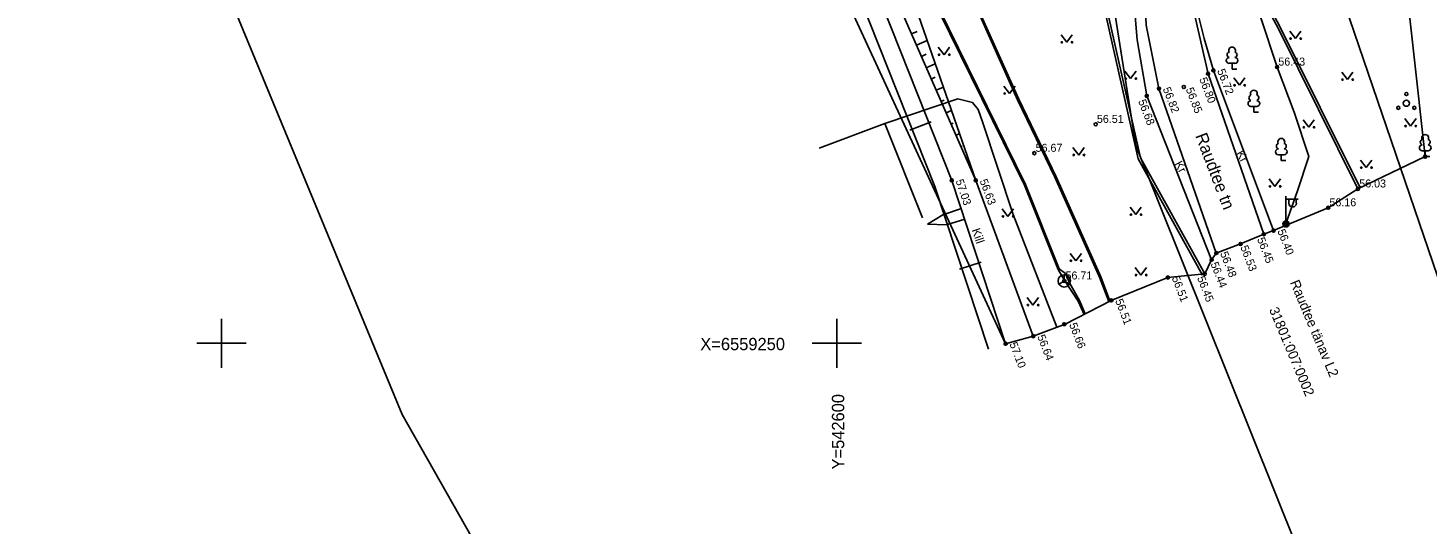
# Model space of a CAD drawing. Extents: x 542320 to 543602, y 6558748 to 6559969.
# Drawn here: x 542534.3 to 542647.9, y 6559235.3 to 6559275.6 of the extents above; entities that cross this region are included whole.
import ezdxf

# ---------------------------------------------------------------- set-up
doc = ezdxf.new("R2010")
doc.units = 0
for name, color, linetype in [('HALJASTUS', 7, 'Continuous'), ('KORGUS-EH2000', 7, 'Continuous'), ('KPKAABEL', 7, 'Continuous'), ('mootpiir', 7, 'Continuous'), ('MPKAABEL', 7, 'Continuous'), ('PIIR', 7, 'Continuous'), ('POST', 7, 'Continuous'), ('PUU', 7, 'Continuous'), ('RDT', 7, 'Continuous'), ('RELJEEF', 7, 'Continuous'), ('SIKAEV', 7, 'Continuous'), ('SITRASS', 7, 'Continuous'), ('TEE', 7, 'Continuous'), ('VORK', 7, 'Continuous')]:
    doc.layers.add(name, color=color, linetype=linetype)

# ---------------------------------------------------------------- blocks, each defined once
blk = doc.blocks.new('VKORIS')
for p, q in [((0, 4), (0, -4)), ((-4, 0), (4, 0))]:
    blk.add_line(p, q)
blk = doc.blocks.new('SIKAEV')
for p, q in [((0, 0), (-0.83, -0.55)), ((0, 1), (0, 0)), ((0, 0), (0.83, -0.55))]:
    blk.add_line(p, q)
blk.add_circle((0, 0), 1)
blk = doc.blocks.new('LEHTP1')
for p, q in [((0.48, 0.95), (-0.48, 0.95)), ((0, 0), (0, 0.95)), ((0.76, 0), (0, 0))]:
    blk.add_line(p, q)
for centre, radius, start, end in [((-0.34, 2.35), 0.465, 109.0217, 253.1415), ((0, 3.04), 0.554, 332.5799, 207.4201), ((0.34, 2.35), 0.465, 286.8508, 70.9859), ((-0.47, 1.42), 0.475, 90.0016, 269.3953), ((0.47, 1.42), 0.475, 270.6047, 89.9984)]:
    blk.add_arc(centre, radius, start, end)
blk = doc.blocks.new('PQQSAS')
for centre, radius in [((0, 0), 0.5), ((0, 1.5), 0.25), ((-1.3, -0.75), 0.25), ((1.3, -0.75), 0.25)]:
    blk.add_circle(centre, radius)
blk = doc.blocks.new('MEPOST')
for radius in [0.5, 0.45, 0.4, 0.35, 0.3, 0.25, 0.2, 0.15, 0.1, 0.05]:
    blk.add_circle((0, 0), radius)
blk = doc.blocks.new('VAPOST')
for p, q in [((0, 0.5), (0, 4.5)), ((0, 4), (2, 4)), ((0.45, 3.36), (0.45, 4)), ((1.68, 3.36), (1.68, 4))]:
    blk.add_line(p, q)
blk.add_arc((1.07, 3.36), 0.613, 180, 0)
blk = doc.blocks.new('MURU')
for p, q in [((-0.93, 1.21), (0, 0)), ((0, 0), (0.89, 1.21))]:
    blk.add_line(p, q)
for centre in [(-0.8, 0), (0.86, 0)]:
    blk.add_circle(centre, 0.11)
blk = doc.blocks.new('RING02')
blk.add_circle((0, 0), 0.25)

msp = doc.modelspace()

# ---------------------------------------------------------------- linework, layer by layer
at = {"layer": 'KPKAABEL'}
for points in [[(542592.52, 6559362.45), (542597.55, 6559351.95), (542600.14, 6559344.37), (542606.12, 6559332.4), (542610.86, 6559323.16), (542616.27, 6559312.94), (542622.06, 6559301.81), (542626.97, 6559292.38), (542631.61, 6559283.75), (542633.96, 6559279.16), (542635.84, 6559275.61), (542642.33, 6559262.55)], [(542592.7, 6559362.53), (542597.73, 6559352.02), (542600.32, 6559344.44), (542606.3, 6559332.49), (542611.03, 6559323.25), (542616.45, 6559313.04), (542622.24, 6559301.9), (542627.15, 6559292.48), (542631.79, 6559283.85), (542634.14, 6559279.25), (542636.01, 6559275.7), (542642.5, 6559262.64)], [(542629.71, 6559255.55), (542624.46, 6559265.01), (542621.33, 6559279), (542619.56, 6559289.35), (542615.6, 6559299.12), (542610.38, 6559310.03), (542605.39, 6559319.87), (542600.37, 6559330.02), (542596.98, 6559338.2), (542596.38, 6559342.12), (542596.81, 6559346.97), (542595.76, 6559350.64), (542591.14, 6559359.29), (542590.25, 6559360.8)], [(542629.88, 6559255.64), (542624.65, 6559265.09), (542621.53, 6559279.04), (542619.76, 6559289.41), (542615.79, 6559299.2), (542610.56, 6559310.12), (542605.57, 6559319.96), (542600.55, 6559330.11), (542597.18, 6559338.25), (542596.58, 6559342.13), (542597.01, 6559346.99), (542595.94, 6559350.72), (542591.32, 6559359.39), (542590.42, 6559360.9)]]:
    msp.add_lwpolyline(points, dxfattribs=at)
at = {"layer": 'mootpiir'}
msp.add_lwpolyline([(542580.6, 6559350.5), (542576.13, 6559347.21), (542573.57, 6559344.25), (542570.53, 6559343.48), (542613.7, 6559249.97), (542615.95, 6559250.58), (542618.55, 6559251.55), (542622.29, 6559253.49), (542626.88, 6559255.35), (542629.88, 6559255.64), (542630.44, 6559256.8), (542630.82, 6559257.34), (542632.79, 6559258.08), (542634.68, 6559258.87), (542635.47, 6559259.16), (542639.91, 6559261.02), (542642.33, 6559262.55), (542647.79, 6559265.18), (542644.8, 6559292.13), (542641.56, 6559300.61), (542636.85, 6559320.34), (542627.62, 6559356.73)], dxfattribs=at)
at = {"layer": 'MPKAABEL'}
for p, q in [((542609.81, 6559269.89), (542603.89, 6559267.86)), ((542609.81, 6559269.89), (542603.89, 6559267.86)), ((542611.02, 6559269.59), (542609.81, 6559269.89)), ((542611.02, 6559269.59), (542609.81, 6559269.89)), ((542611.46, 6559269.02), (542611.02, 6559269.59)), ((542611.46, 6559269.02), (542611.02, 6559269.59)), ((542611.82, 6559268.01), (542611.46, 6559269.02)), ((542611.82, 6559268.01), (542611.46, 6559269.02)), ((542603.89, 6559267.86), (542598.56, 6559265.87)), ((542603.89, 6559267.86), (542598.56, 6559265.87)), ((542606.96, 6559260.19), (542603.89, 6559267.86)), ((542606.96, 6559260.19), (542603.89, 6559267.86)), ((542614.31, 6559260.47), (542611.82, 6559268.01)), ((542614.31, 6559260.47), (542611.82, 6559268.01)), ((542608.59, 6559260.44), (542610.12, 6559260.97)), ((542617.86, 6559251.3), (542614.31, 6559260.47)), ((542617.86, 6559251.3), (542614.31, 6559260.47)), ((542607.36, 6559259.69), (542608.59, 6559260.44)), ((542607.36, 6559259.69), (542608.59, 6559260.44)), ((542607.36, 6559259.69), (542608.89, 6559259.62)), ((542607.36, 6559259.69), (542608.89, 6559259.62)), ((542608.89, 6559259.62), (542610.4, 6559260.08))]:
    msp.add_line(p, q, dxfattribs=at)
for points in [[(542622.09, 6559253.39), (542621.33, 6559255.37), (542617.71, 6559263.5), (542614.68, 6559269.79), (542611.09, 6559277.81), (542606.04, 6559289.6), (542605.82, 6559290.91), (542605.06, 6559292.01), (542601.33, 6559298.32), (542596.16, 6559308.1), (542592.3, 6559315.73), (542590.05, 6559320.2), (542585.68, 6559328.5), (542583.04, 6559333.5), (542580.39, 6559338.55), (542578.35, 6559342.4), (542575.83, 6559346.87)], [(542622.18, 6559253.44), (542621.43, 6559255.41), (542617.8, 6559263.54), (542614.77, 6559269.84), (542611.18, 6559277.85), (542606.14, 6559289.62), (542605.91, 6559290.95), (542605.15, 6559292.07), (542601.41, 6559298.37), (542596.24, 6559308.15), (542592.39, 6559315.78), (542590.14, 6559320.24), (542585.77, 6559328.55), (542583.13, 6559333.54), (542580.48, 6559338.6), (542578.44, 6559342.45), (542575.9, 6559346.95)], [(542636.48, 6559259.71), (542637.41, 6559262.41), (542638.34, 6559265.2), (542637.15, 6559268.8), (542635.76, 6559272.46), (542634.44, 6559276.46)]]:
    msp.add_lwpolyline(points, dxfattribs=at)
at = {"layer": 'PIIR'}
for points in [[(542661.19, 6559057.3), (542631.86, 6559131.08), (542623.73, 6559151.51), (542622.55, 6559153.44), (542596.44, 6559196.28), (542582.74, 6559212.35), (542564.67, 6559244.2), (542533.12, 6559320.57), (542531.79, 6559323.45), (542465.95, 6559465.71), (542406.39, 6559583.67)], [(542456.68, 6559581.07), (542523.83, 6559477.46), (542537.52, 6559453.62), (542591.81, 6559358.92), (542597.79, 6559348.5), (542599.76, 6559343.89), (542619.08, 6559298.96), (542624.28, 6559266.08), (542637.46, 6559233.17), (542680, 6559143.81), (542700.43, 6559093.84), (542700.92, 6559090.29), (542704.02, 6559067.82)], [(542632.63, 6559302.87), (542612.16, 6559350.51), (542632.02, 6559361.13), (542651.63, 6559324.28), (542646.33, 6559321.44), (542665.85, 6559284.72), (542671.39, 6559287.65), (542689.34, 6559253.48), (542704.9, 6559215.47), (542674.63, 6559203.23), (542672.45, 6559208.6), (542665.71, 6559205.86), (542632.63, 6559302.87)], [(542612.16, 6559350.51), (542632.63, 6559302.87), (542665.71, 6559205.86), (542667.87, 6559200.49), (542682.31, 6559164.31), (542683.94, 6559160.9), (542699.54, 6559124.27), (542718.47, 6559078.4), (542700.92, 6559090.29), (542700.43, 6559093.84), (542680, 6559143.81), (542637.46, 6559233.17), (542624.28, 6559266.08), (542619.08, 6559298.96), (542599.76, 6559343.89), (542612.16, 6559350.51)]]:
    msp.add_lwpolyline(points, dxfattribs=at)
at = {"layer": 'RDT'}
for points in [[(542570.53, 6559343.48), (542587.32, 6559311.76), (542594.42, 6559298.32), (542600.93, 6559284.44), (542609.33, 6559263.25), (542613.7, 6559249.97)], [(542569.24, 6559342.8), (542586.03, 6559311.08), (542593.11, 6559297.67), (542599.58, 6559283.86), (542607.95, 6559262.76), (542612.31, 6559249.52)], [(542605.93, 6559267.32), (542607.66, 6559268)], [(542609.96, 6559256.02), (542611.73, 6559256.6)]]:
    msp.add_lwpolyline(points, dxfattribs=at)
at = {"layer": 'RELJEEF'}
for points in [[(542611.28, 6559263.25), (542601.77, 6559284.94), (542595.44, 6559298.86), (542588.13, 6559312.87), (542578.07, 6559334.39), (542577.88, 6559336.16), (542579.74, 6559338.2), (542583.57, 6559340.23), (542588.18, 6559342.44), (542591.62, 6559344.19)], [(542591.62, 6559344.19), (542589.04, 6559341.17), (542585.55, 6559339.38), (542581.61, 6559337.24), (542580.48, 6559335.13), (542584.56, 6559325.43), (542590.14, 6559315.73), (542599.48, 6559301.09), (542603.51, 6559285.65), (542611.28, 6559263.25)], [(542606.06, 6559275.15), (542606.53, 6559275.36)], [(542606.46, 6559274.24), (542607.33, 6559274.62)], [(542606.86, 6559273.32), (542607.26, 6559273.5)], [(542607.26, 6559272.4), (542607.99, 6559272.72)], [(542607.66, 6559271.49), (542607.99, 6559271.63)], [(542608.06, 6559270.57), (542608.65, 6559270.83)], [(542608.47, 6559269.66), (542608.72, 6559269.77)], [(542608.87, 6559268.74), (542609.3, 6559268.93)], [(542609.27, 6559267.82), (542609.45, 6559267.9)], [(542609.67, 6559266.91), (542609.96, 6559267.04)], [(542610.07, 6559265.99), (542610.18, 6559266.04)], [(542610.47, 6559265.08), (542610.62, 6559265.14)]]:
    msp.add_lwpolyline(points, dxfattribs=at)
at = {"layer": 'SITRASS'}
for points in [[(542620.08, 6559252.35), (542619.61, 6559253.42), (542618.45, 6559255.17), (542617.97, 6559256.01), (542615.23, 6559262.86), (542599.65, 6559294.6), (542592.25, 6559308.15), (542591.92, 6559308.73), (542590.02, 6559312.16), (542581.41, 6559328.23), (542578.73, 6559334.14), (542575.62, 6559340.11), (542573.23, 6559344.17)], [(542620.17, 6559252.39), (542619.7, 6559253.47), (542618.92, 6559254.85), (542618.56, 6559255.68), (542618.06, 6559256.05), (542615.33, 6559262.9), (542599.74, 6559294.65), (542592.34, 6559308.19), (542592.29, 6559308.9), (542591.74, 6559309.32), (542590.11, 6559312.21), (542581.5, 6559328.28), (542578.82, 6559334.18), (542575.71, 6559340.16), (542573.33, 6559344.19)]]:
    msp.add_lwpolyline(points, dxfattribs=at)
at = {"layer": 'TEE'}
for points in [[(542624.1, 6559367.1), (542623.09, 6559366.62), (542619.66, 6559364.74), (542606.49, 6559357.53), (542598.93, 6559352.72), (542596.39, 6559351.26), (542597.48, 6559348.27), (542599.1, 6559344.51), (542601.52, 6559338.8), (542604.02, 6559333.45), (542609.84, 6559322.48), (542616.48, 6559310.11), (542621.37, 6559299.41), (542623.15, 6559294.6), (542623.73, 6559292.74), (542624.33, 6559289.25), (542624.92, 6559285.03), (542624.92, 6559280.09), (542625.11, 6559275.88), (542626.16, 6559270.71), (542630.82, 6559257.34)], [(542634.68, 6559258.87), (542630.15, 6559271.92), (542629.13, 6559276.41), (542628.98, 6559278.99), (542628.99, 6559283.21), (542628.79, 6559287.96), (542628.21, 6559291.8), (542627.22, 6559295.85), (542627.15, 6559296.26), (542626, 6559299.92), (542624.09, 6559304.14), (542620.26, 6559312.26), (542613.87, 6559324.5), (542608.18, 6559335.16), (542606.43, 6559338.99), (542605.72, 6559341.19), (542605.4, 6559342.93), (542605.27, 6559345.1), (542605.47, 6559347.12), (542606.08, 6559349.35), (542607.84, 6559352.39), (542608.75, 6559353.7), (542625.26, 6559363)], [(542625.59, 6559362.35), (542608.76, 6559352.38), (542607.28, 6559350.3), (542606.17, 6559347.79), (542605.93, 6559345.3), (542606.43, 6559342.48), (542606.99, 6559340.5), (542609.2, 6559335.67), (542614.6, 6559324.83), (542620.94, 6559312.64), (542624.6, 6559304.52), (542626.86, 6559298.57), (542627.69, 6559295.96), (542628.38, 6559292.61), (542629.03, 6559288.15), (542629.33, 6559283.8), (542629.22, 6559279.54), (542629.4, 6559276.51), (542629.82, 6559274.79), (542630.58, 6559272.19), (542635.47, 6559259.16)], [(542630.44, 6559256.8), (542625.17, 6559270.11), (542624.38, 6559274.67), (542623.87, 6559280.79), (542623.67, 6559288.88), (542622.43, 6559294.2), (542622.36, 6559295.06), (542620.97, 6559299.05), (542615.72, 6559309.7), (542609.02, 6559322.07), (542603.29, 6559332.96), (542601.01, 6559337.65), (542600.27, 6559338.02), (542599.29, 6559338.5), (542598.12, 6559339.73), (542596.15, 6559343.68), (542594.87, 6559346.8)], [(542615.95, 6559250.58), (542611.28, 6559263.25)]]:
    msp.add_lwpolyline(points, dxfattribs=at)

# ---------------------------------------------------------------- block references
at = {"layer": 'HALJASTUS', "xscale": 0.5, "yscale": 0.5}
for p in [(542637.25, 6559274.78), (542618.67, 6559274.48), (542608.7, 6559273.46), (542623.86, 6559271.52), (542641.47, 6559271.44), (542614.03, 6559270.31), (542632.7, 6559270.98), (542638.33, 6559267.57), (542646.6, 6559267.66), (542619.64, 6559265.31), (542643, 6559264.29), (542635.58, 6559262.76), (542613.89, 6559260.32), (542624.28, 6559260.46), (542619.41, 6559256.71), (542624.7, 6559255.55), (542615.92, 6559253.11)]:
    msp.add_blockref('MURU', p, dxfattribs=at)
at = {"layer": 'KORGUS-EH2000', "xscale": 0.5, "yscale": 0.5}
for p in [(542630.15, 6559271.92), (542630.58, 6559272.19), (542635.76, 6559272.46), (542626.16, 6559270.71), (542628.18, 6559270.84), (542625.17, 6559270.11), (542621.02, 6559267.81), (542616.04, 6559265.46), (542647.79, 6559265.18), (542609.33, 6559263.25), (542611.28, 6559263.25), (542642.33, 6559262.55), (542639.91, 6559261.02), (542632.79, 6559258.08), (542634.68, 6559258.87), (542635.47, 6559259.16), (542630.82, 6559257.34), (542630.44, 6559256.8), (542618.47, 6559255.07), (542626.88, 6559255.35), (542629.88, 6559255.64), (542622.29, 6559253.49), (542618.47, 6559251.55), (542615.95, 6559250.58), (542613.7, 6559249.97)]:
    msp.add_blockref('RING02', p, dxfattribs=at)
at = {"layer": 'POST', "xscale": 0.5, "yscale": 0.5}
for name in ['VAPOST', 'MEPOST']:
    msp.add_blockref(name, (542636.48, 6559259.71), dxfattribs=at)
at = {"layer": 'PUU', "xscale": 0.5, "yscale": 0.5}
for name, p in [('LEHTP1', (542632.1, 6559272.29)), ('LEHTP1', (542633.87, 6559268.78)), ('PQQSAS', (542646.26, 6559269.52)), ('LEHTP1', (542636.1, 6559264.86)), ('LEHTP1', (542647.79, 6559265.18))]:
    msp.add_blockref(name, p, dxfattribs=at)
at = {"layer": 'SIKAEV', "xscale": 0.5, "yscale": 0.5}
msp.add_blockref('SIKAEV', (542618.47, 6559255.07), dxfattribs=at)
at = {"layer": 'VORK', "xscale": 0.5, "yscale": 0.5}
for p in [(542550, 6559250), (542600, 6559250)]:
    msp.add_blockref('VKORIS', p, dxfattribs=at)

# ---------------------------------------------------------------- texts
at = {"layer": 'KORGUS-EH2000'}
for s, p in [('56.43', (542635.86, 6559272.58)), ('56.51', (542621.12, 6559267.92)), ('56.67', (542616.14, 6559265.57)), ('56.03', (542642.43, 6559262.67)), ('56.16', (542640.01, 6559261.14)), ('56.71', (542618.57, 6559255.19))]:
    msp.add_text(s, height=0.65, dxfattribs=at).set_placement(p)
for s, rotation, p in [('56.72', 291.0461, (542630.88, 6559272.17)), ('56.82', 291.0461, (542626.46, 6559270.69)), ('56.85', 291.0461, (542628.33, 6559270.66)), ('56.80', 291.0461, (542629.42, 6559271.48)), ('56.68', 291.0461, (542624.46, 6559269.69)), ('57.03', 288.6785, (542609.63, 6559263.22)), ('56.63', 290.3438, (542611.58, 6559263.22)), ('56.45', 291.0461, (542634.12, 6559258.47)), ('56.40', 291.0461, (542635.77, 6559259.14)), ('56.48', 291.0461, (542631.12, 6559257.32)), ('56.53', 291.0461, (542632.76, 6559257.82)), ('56.44', 291.0461, (542630.34, 6559256.47)), ('56.51', 291.0461, (542627.19, 6559255.32)), ('56.45', 291.0461, (542629.25, 6559255.32)), ('56.51', 291.0461, (542622.59, 6559253.47)), ('56.66', 291.0461, (542618.85, 6559251.53)), ('56.64', 291.0461, (542616.26, 6559250.56)), ('57.10', 291.0461, (542614, 6559249.95))]:
    msp.add_text(s, height=0.65, rotation=rotation, dxfattribs=at).set_placement(p)
at = {"layer": 'PIIR'}
for s, p in [('Raudtee tänav L2', (542636.79, 6559254.95)), ('31801:007:0002', (542635.09, 6559252.74))]:
    msp.add_text(s, height=0.8, rotation=292.7711, dxfattribs=at).set_placement(p)
at = {"layer": 'TEE'}
for s, height, rotation, p in [('Raudtee tn', 1, 290.8918, (542629.09, 6559266.88)), ('Kr', 0.7, 299.4082, (542632.4, 6559265.45)), ('Kr', 0.7, 299.4082, (542627.39, 6559264.59)), ('Kill', 0.7, 288.735, (542610.94, 6559259.22))]:
    msp.add_text(s, height=height, rotation=rotation, dxfattribs=at).set_placement(p)
at = {"layer": 'VORK'}
msp.add_text('X=6559250', height=1, dxfattribs=at).set_placement((542588.9, 6559249.44))
msp.add_text('Y=542600', height=1, rotation=90, dxfattribs=at).set_placement((542600.59, 6559239.74))

doc.saveas('drawing.dxf')
